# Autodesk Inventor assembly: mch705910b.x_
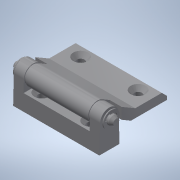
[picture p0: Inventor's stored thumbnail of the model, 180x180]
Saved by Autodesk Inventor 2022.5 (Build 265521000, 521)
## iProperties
Part Number: mch705910b.x_
Material: 一般
Document SubType Name: Assembly
Designer: ImaoCorp
Sending System: SOLIDWORKS 2017-2017317
MC: AMD64
MC_MODEL: Intel64 Family 6 Model 60 Stepping 3, GenuineIntel
OS: Windows_NT
FRU: Parasolid Version 29.0, build 201,  4-17-2017
FORMAT: text
GUISE: transmit
KEY: mch705910b
FILE: mch705910b.x_t
DATE: Fri Jul 26 11:41:51 2019
Author: ImaoCorp
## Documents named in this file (4)
- X:\14_SW2022-Inv2022\00_全2023-1023新製品(TCC)まで\m\mch705910b\MCH705910B.iam
- X:\14_SW2022-Inv2022\00_全2023-1023新製品(TCC)まで\m\mch705910b\mch705910b_01.ipt
- X:\14_SW2022-Inv2022\00_全2023-1023新製品(TCC)まで\m\mch705910b\mch705910b_02.ipt
- X:\14_SW2022-Inv2022\00_全2023-1023新製品(TCC)まで\m\mch705910b\mch705910b_03.ipt
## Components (3 placed, 3 different names)
1. mch705910b_01
2. mch705910b_02
3. mch705910b_03
